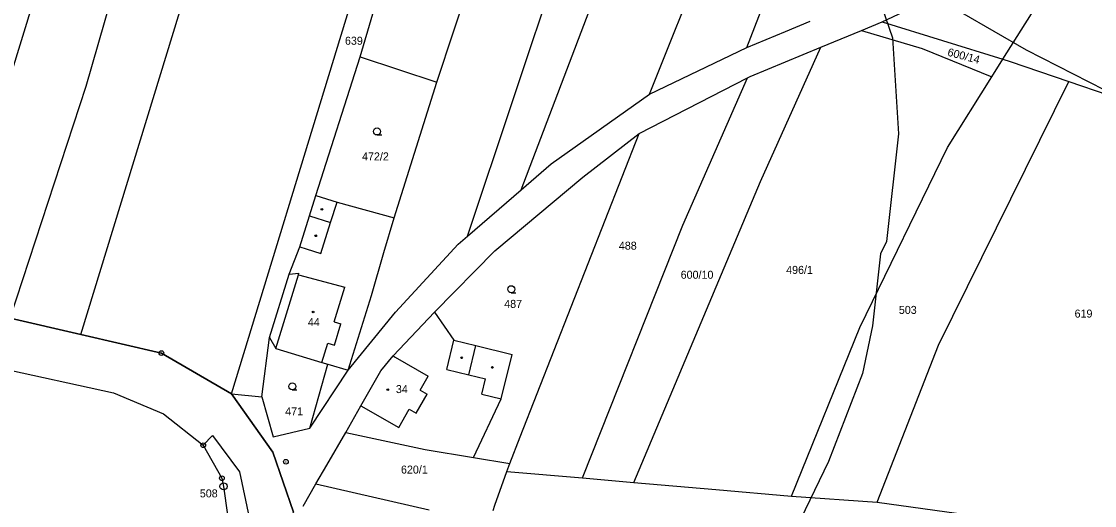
# Model space of a CAD drawing. Extents: x -743888 to -742027, y -1128394 to -1126768.
# Drawn here: x -742825.9 to -742597.9, y -1127193 to -1127090.1 of the extents above; entities that cross this region are included whole.
import ezdxf

# ---------------------------------------------------------------- set-up
doc = ezdxf.new("R2010")
doc.units = 0
for name, color, linetype in [('Vrstva 1', 7, 'Continuous'), ('Vrstva 17', 7, 'Continuous'), ('Vrstva 18', 7, 'Continuous'), ('Vrstva 19', 7, 'Continuous'), ('Vrstva 24', 7, 'Continuous'), ('Vrstva 25', 7, 'Continuous'), ('Vrstva 3', 7, 'Continuous'), ('Vrstva 37', 7, 'Continuous'), ('Vrstva 4', 7, 'Continuous'), ('Vrstva 52', 7, 'Continuous'), ('Vrstva 6', 7, 'Continuous')]:
    doc.layers.add(name, color=color, linetype=linetype)

msp = doc.modelspace()

# ---------------------------------------------------------------- linework, layer by layer
at = {"layer": 'Vrstva 1'}
for points in [[(-742737.64, -1127102.99), (-742708.78, -1127015.67)], [(-742781.25, -1127169.22), (-742734.68, -1127016.73)], [(-742753.9, -1127097.67), (-742730.63, -1127018.43)], [(-742692.49, -1127105.57), (-742668.53, -1127045.71)], [(-742643.05, -1127090.21), (-742621.7, -1127080.04)], [(-742671.78, -1127095.63), (-742667.08, -1127083.34)], [(-742663.55, -1127092.23), (-742658.33, -1127090.03)], [(-742647.45, -1127092.03), (-742643.05, -1127090.21)], [(-742643.05, -1127090.21), (-742617.44, -1127098.12)], [(-742671.78, -1127095.63), (-742663.55, -1127092.23)], [(-742656.1, -1127095.61), (-742647.45, -1127092.03)], [(-742763.33, -1127127.12), (-742753.9, -1127097.67)], [(-742753.9, -1127097.67), (-742737.64, -1127102.99)], [(-742692.49, -1127105.57), (-742671.78, -1127095.63)], [(-742671.07, -1127101.8), (-742656.1, -1127095.61)], [(-742617.44, -1127098.12), (-742615.85, -1127098.61)], [(-742615.85, -1127098.61), (-742603.37, -1127102.87)], [(-742694.65, -1127113.94), (-742671.65, -1127102.1)], [(-742671.65, -1127102.1), (-742671.07, -1127101.8)], [(-742746.73, -1127131.84), (-742737.64, -1127102.99)], [(-742603.37, -1127102.87), (-742595.15, -1127105.68)], [(-742713.34, -1127120.39), (-742692.49, -1127105.57)], [(-742719.91, -1127178.34), (-742694.65, -1127113.94)], [(-742706.66, -1127123.2), (-742694.65, -1127113.94)], [(-742719.74, -1127125.92), (-742713.34, -1127120.39)], [(-742725.34, -1127138.85), (-742706.66, -1127123.2)], [(-742764.69, -1127131.41), (-742763.33, -1127127.12)], [(-742763.33, -1127127.12), (-742758.85, -1127128.54)], [(-742731.14, -1127135.75), (-742719.74, -1127125.92)], [(-742758.85, -1127128.54), (-742746.73, -1127131.84)], [(-742766.77, -1127137.99), (-742764.69, -1127131.41)], [(-742748.92, -1127139.17), (-742746.73, -1127131.84)], [(-742733.12, -1127137.46), (-742731.14, -1127135.75)], [(-742769.01, -1127143.81), (-742766.77, -1127137.99)], [(-742746.45, -1127151.91), (-742733.12, -1127137.46)], [(-742738.13, -1127151.87), (-742725.34, -1127138.85)], [(-742751.52, -1127148.31), (-742748.92, -1127139.17)], [(-742773.17, -1127157.23), (-742769.01, -1127143.81)], [(-742756.51, -1127164.2), (-742751.52, -1127148.31)], [(-742756.51, -1127164.2), (-742746.45, -1127151.91)], [(-742746.92, -1127161.19), (-742738.13, -1127151.87)], [(-742738.13, -1127151.87), (-742734.01, -1127157.82)], [(-742828.27, -1127153.14), (-742813.25, -1127156.61)], [(-742813.25, -1127156.61), (-742796.14, -1127160.57)], [(-742774.85, -1127169.87), (-742773.17, -1127157.23)], [(-742773.17, -1127157.23), (-742771.82, -1127159.58)], [(-742734.01, -1127157.82), (-742729.37, -1127158.96)], [(-742729.37, -1127158.96), (-742721.67, -1127160.86)], [(-742796.14, -1127160.57), (-742781.25, -1127169.22)], [(-742771.82, -1127159.58), (-742762.06, -1127162.55)], [(-742749.51, -1127164.33), (-742746.92, -1127161.19)], [(-742723.99, -1127170.28), (-742721.67, -1127160.86)], [(-742830.93, -1127163.61), (-742806.35, -1127169.04)], [(-742764.59, -1127176.5), (-742760.77, -1127162.93)], [(-742762.06, -1127162.55), (-742760.77, -1127162.93)], [(-742764.59, -1127176.5), (-742756.51, -1127164.2)], [(-742753.8, -1127171.75), (-742749.51, -1127164.33)], [(-742806.35, -1127169.04), (-742795.67, -1127173.47)], [(-742781.25, -1127169.22), (-742774.85, -1127169.87)], [(-742781.25, -1127169.22), (-742772.5, -1127181.64)], [(-742774.85, -1127169.87), (-742772.44, -1127178.33)], [(-742729.83, -1127182.75), (-742723.99, -1127170.28)], [(-742756.98, -1127177.44), (-742753.8, -1127171.75)], [(-742795.67, -1127173.47), (-742787.26, -1127180.14)], [(-742772.44, -1127178.33), (-742764.59, -1127176.5)], [(-742761, -1127184.37), (-742756.98, -1127177.44)], [(-742756.98, -1127177.44), (-742740.1, -1127181.07)], [(-742722.13, -1127184.01), (-742719.91, -1127178.34)], [(-742787.26, -1127180.14), (-742783.29, -1127187.16)], [(-742772.5, -1127181.64), (-742768.06, -1127194.37)], [(-742740.1, -1127181.07), (-742729.83, -1127182.75)], [(-742763.32, -1127188.38), (-742761, -1127184.37)], [(-742729.83, -1127182.75), (-742722.13, -1127184.01)], [(-742722.77, -1127185.76), (-742722.13, -1127184.01)], [(-742725.36, -1127192.86), (-742722.77, -1127185.76)], [(-742783.29, -1127187.16), (-742782.95, -1127188.88)], [(-742782.95, -1127188.88), (-742782.14, -1127194.94)], [(-742766.04, -1127193.06), (-742763.32, -1127188.38)], [(-742763.32, -1127188.38), (-742739.28, -1127193.88)], [(-742725.69, -1127194.04), (-742725.36, -1127192.86)]]:
    msp.add_lwpolyline(points, dxfattribs=at)
at = {"layer": 'Vrstva 24'}
for p, q in [((-742796.19, -1127160.57), (-742796.09, -1127160.57)), ((-742787.31, -1127180.14), (-742787.21, -1127180.14)), ((-742769.76, -1127183.65), (-742769.66, -1127183.65)), ((-742783.34, -1127187.16), (-742783.24, -1127187.16)), ((-742783, -1127188.88), (-742782.9, -1127188.88))]:
    msp.add_line(p, q, dxfattribs=at)
for centre, radius in [((-742796.14, -1127160.57), 0.499), ((-742787.26, -1127180.14), 0.499), ((-742769.71, -1127183.65), 0.499), ((-742783.29, -1127187.16), 0.499), ((-742782.95, -1127188.88), 0.756)]:
    msp.add_circle(centre, radius, dxfattribs=at)
at = {"layer": 'Vrstva 25'}
for p, q in [((-742750.35, -1127114.24), (-742749.35, -1127114.24)), ((-742721.83, -1127147.76), (-742720.83, -1127147.76)), ((-742768.35, -1127168.4), (-742767.35, -1127168.4))]:
    msp.add_line(p, q, dxfattribs=at)
for centre, radius in [((-742750.35, -1127113.49), 0.75), ((-742762.06, -1127130.05), 0.175), ((-742763.35, -1127135.65), 0.175), ((-742721.83, -1127147.01), 0.75), ((-742763.92, -1127151.83), 0.175), ((-742732.37, -1127161.57), 0.175), ((-742725.85, -1127163.62), 0.175), ((-742768.35, -1127167.65), 0.75), ((-742748.06, -1127168.34), 0.175)]:
    msp.add_circle(centre, radius, dxfattribs=at)
at = {"layer": 'Vrstva 3'}
for points in [[(-742771.82, -1127159.58), (-742767.06, -1127143.93)], [(-742767.06, -1127143.93), (-742757.2, -1127146.56)], [(-742759.44, -1127153.94), (-742757.2, -1127146.56)], [(-742759.44, -1127153.94), (-742758.01, -1127154.38)], [(-742759.39, -1127158.92), (-742758.01, -1127154.38)], [(-742762.06, -1127162.55), (-742760.82, -1127158.48)], [(-742760.82, -1127158.48), (-742759.39, -1127158.92)], [(-742771.82, -1127159.58), (-742762.06, -1127162.55)], [(-742749.51, -1127164.33), (-742746.92, -1127161.19)], [(-742746.92, -1127161.19), (-742746.49, -1127161.44)], [(-742746.49, -1127161.44), (-742739.46, -1127165.49)], [(-742753.8, -1127171.75), (-742749.51, -1127164.33)], [(-742741.16, -1127168.43), (-742739.46, -1127165.49)], [(-742741.16, -1127168.43), (-742739.69, -1127169.28)], [(-742742.03, -1127173.35), (-742739.69, -1127169.28)], [(-742753.8, -1127171.75), (-742745.75, -1127176.39)], [(-742745.75, -1127176.39), (-742743.5, -1127172.5)], [(-742743.5, -1127172.5), (-742742.03, -1127173.35)]]:
    msp.add_lwpolyline(points, dxfattribs=at)
at = {"layer": 'Vrstva 37'}
for centre in [(-742763.92, -1127151.83), (-742748.06, -1127168.34)]:
    msp.add_circle(centre, 0.175, dxfattribs=at)
at = {"layer": 'Vrstva 4'}
for points in [[(-742760.21, -1127132.83), (-742758.85, -1127128.54)], [(-742764.69, -1127131.41), (-742760.21, -1127132.83)], [(-742762.29, -1127139.41), (-742760.21, -1127132.83)], [(-742766.77, -1127137.99), (-742765.39, -1127138.43)], [(-742765.39, -1127138.43), (-742762.29, -1127139.41)], [(-742771.82, -1127159.58), (-742767.06, -1127143.93)], [(-742769.01, -1127143.81), (-742766.96, -1127143.59)], [(-742767.06, -1127143.93), (-742766.96, -1127143.59)], [(-742767.06, -1127143.93), (-742757.2, -1127146.56)], [(-742759.44, -1127153.94), (-742757.2, -1127146.56)], [(-742759.44, -1127153.94), (-742758.01, -1127154.38)], [(-742759.39, -1127158.92), (-742758.01, -1127154.38)], [(-742762.06, -1127162.55), (-742760.82, -1127158.48)], [(-742760.82, -1127158.48), (-742759.39, -1127158.92)], [(-742735.55, -1127164.03), (-742734.01, -1127157.82)], [(-742730.82, -1127165.2), (-742729.37, -1127158.96)], [(-742746.92, -1127161.19), (-742746.49, -1127161.44)], [(-742746.49, -1127161.44), (-742739.46, -1127165.49)], [(-742760.77, -1127162.93), (-742756.51, -1127164.2)], [(-742741.16, -1127168.43), (-742739.46, -1127165.49)], [(-742735.55, -1127164.03), (-742730.82, -1127165.2)], [(-742730.82, -1127165.2), (-742727.31, -1127166.06)], [(-742728.1, -1127169.27), (-742727.31, -1127166.06)], [(-742741.16, -1127168.43), (-742739.69, -1127169.28)], [(-742742.03, -1127173.35), (-742739.69, -1127169.28)], [(-742728.1, -1127169.27), (-742723.99, -1127170.28)], [(-742753.8, -1127171.75), (-742745.75, -1127176.39)], [(-742745.75, -1127176.39), (-742743.5, -1127172.5)], [(-742743.5, -1127172.5), (-742742.03, -1127173.35)], [(-742787.26, -1127180.14), (-742785.27, -1127178.06)], [(-742785.27, -1127178.06), (-742779.59, -1127185.83)], [(-742779.59, -1127185.83), (-742777.49, -1127195.5)]]:
    msp.add_lwpolyline(points, dxfattribs=at)
at = {"layer": 'Vrstva 52'}
for points in [[(-742646.81, -1127076.25), (-742640.88, -1127093.63), (-742639.56, -1127114), (-742642.13, -1127136.88), (-742643.44, -1127139.5), (-742645.13, -1127154.75), (-742647.25, -1127164.88), (-742654.44, -1127183.63), (-742666.31, -1127208.13), (-742674.05, -1127219.73), (-742674.81, -1127220.88), (-742680.75, -1127227.25), (-742677.75, -1127229.38)], [(-742646.81, -1127076.25), (-742612.44, -1127096.13), (-742592.5, -1127106.38), (-742546.69, -1127126.75), (-742505.56, -1127139.5), (-742478.38, -1127150), (-742453.38, -1127158.5), (-742442.31, -1127163.63), (-742435.56, -1127165.75), (-742424.06, -1127170.88), (-742339.69, -1127206.5), (-742305.31, -1127215.88), (-742247.63, -1127232), (-742239.56, -1127234.88), (-742196.25, -1127246), (-742170.81, -1127254), (-742159.38, -1127257.38), (-742097.81, -1127270.5)], [(-743021.39, -1127124.08), (-742966.69, -1127134.89), (-742939.19, -1127141.02), (-742879.66, -1127154.29), (-742876.73, -1127154.94), (-742831.39, -1127163.51), (-742830.93, -1127163.61), (-742806.35, -1127169.04), (-742795.67, -1127173.47), (-742787.26, -1127180.14), (-742783.29, -1127187.16), (-742782.95, -1127188.88), (-742782.14, -1127194.94), (-742783.62, -1127204.69), (-742786.61, -1127214.77), (-742804.45, -1127253.23), (-742809.73, -1127263.8), (-742816.8, -1127273.23)], [(-742801.66, -1127269.85), (-742799.73, -1127266.98), (-742793.82, -1127256.75), (-742793.38, -1127256.68), (-742792.94, -1127256.6), (-742791.59, -1127257.13), (-742791.56, -1127257.04), (-742788.68, -1127248.97), (-742785.8, -1127242.82), (-742783.76, -1127237.1), (-742778.23, -1127225.83), (-742776.45, -1127219.31), (-742772.74, -1127212.53), (-742771.21, -1127206.56), (-742768.06, -1127194.37), (-742772.5, -1127181.64), (-742781.25, -1127169.22), (-742796.14, -1127160.57), (-742813.25, -1127156.61), (-742828.27, -1127153.14)]]:
    msp.add_lwpolyline(points, dxfattribs=at)
at = {"layer": 'Vrstva 6'}
for points in [[(-742719.74, -1127125.92), (-742686.48, -1127038.39)], [(-742813.25, -1127156.61), (-742778.25, -1127042.21)], [(-742812.1, -1127103.89), (-742795.18, -1127045)], [(-742842.98, -1127149.74), (-742815.95, -1127061.82)], [(-742617.44, -1127098.12), (-742599.65, -1127069.95)], [(-742731.14, -1127135.75), (-742711.74, -1127077.56)], [(-742647.45, -1127092.03), (-742634.59, -1127095.86)], [(-742668.92, -1127124.1), (-742656.1, -1127095.61)], [(-742634.59, -1127095.86), (-742619.79, -1127101.89)], [(-742619.79, -1127101.89), (-742617.44, -1127098.12)], [(-742685.41, -1127133.42), (-742671.65, -1127102.1)], [(-742629.16, -1127116.92), (-742619.79, -1127101.89)], [(-742828.27, -1127153.14), (-742812.1, -1127103.89)], [(-742631.06, -1127158.9), (-742603.37, -1127102.87)], [(-742647.78, -1127155.16), (-742629.16, -1127116.92)], [(-742695.82, -1127188.09), (-742668.92, -1127124.1)], [(-742706.71, -1127187.05), (-742685.41, -1127133.42)], [(-742662.31, -1127190.95), (-742647.78, -1127155.16)], [(-742644.1, -1127192.22), (-742631.06, -1127158.9)], [(-742722.77, -1127185.76), (-742706.71, -1127187.05)], [(-742706.71, -1127187.05), (-742695.82, -1127188.09)], [(-742695.82, -1127188.09), (-742678.35, -1127189.57)], [(-742678.35, -1127189.57), (-742662.31, -1127190.95)], [(-742662.31, -1127190.95), (-742644.1, -1127192.22)], [(-742644.1, -1127192.22), (-742566.48, -1127203.04)]]:
    msp.add_lwpolyline(points, dxfattribs=at)

# ---------------------------------------------------------------- texts
at = {"layer": 'Vrstva 17'}
msp.add_text('508', height=1.7, dxfattribs=at).set_placement((-742787.99, -1127191.23))
at = {"layer": 'Vrstva 18'}
for s, p in [('639', (-742757.16, -1127095.07)), ('472/2', (-742753.53, -1127119.64)), ('488', (-742698.98, -1127138.6)), ('600/10', (-742685.85, -1127144.78)), ('496/1', (-742663.45, -1127143.75)), ('487', (-742723.33, -1127150.97)), ('503', (-742639.51, -1127152.25)), ('619', (-742602.18, -1127153.03)), ('471', (-742769.85, -1127173.8)), ('620/1', (-742745.26, -1127186.17))]:
    msp.add_text(s, height=1.7, dxfattribs=at).set_placement(p)
msp.add_text('600/14', height=1.7, rotation=345.3298, dxfattribs=at).set_placement((-742629.3, -1127097.37))
at = {"layer": 'Vrstva 19'}
for s, p in [('44', (-742765.04, -1127154.84)), ('34', (-742746.34, -1127169.07))]:
    msp.add_text(s, height=1.7, dxfattribs=at).set_placement(p)

doc.saveas('drawing.dxf')
